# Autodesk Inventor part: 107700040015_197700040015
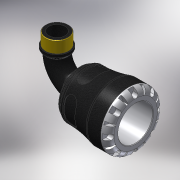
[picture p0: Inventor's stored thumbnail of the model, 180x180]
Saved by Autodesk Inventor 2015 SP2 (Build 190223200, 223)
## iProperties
Created: 2016-12
Part Number: 107700040015_197700040015
Material: PVC-Piping
Description: PLASSON 90° ELBOW WITH MALE INTEGRAL BRASS 40X1.1/2" SERIES 1
Document SubType Name: Modeling
Designer: KIM
Mass: 664.223 g
Surface Area: 733.008 cm^2
Volume: 474.445 cm^3
Density: 1.4 g/cm^3
Appearance: Black Cast
Author: KIM
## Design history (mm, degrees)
derived "1077.ipt"
feature "Solid1::1077.ipt"
tag "TaggingFeature1"
body "Solid1"
other parameters: "d1" = 29.82, "d8" = 59.5, "d13" = 8, "d14" = 8, "d15" = 0, "d17" = 360 deg, "d19" = 8 deg, "d20" = 0.8, "d21" = 0.8, "d22" = 8 deg, "d24" = 0, "d26" = 360 deg, "d33" = 7, "d43" = 54.6, "d51" = 0.7, "d54" = 14, "d55" = 8.8, "d57" = 15.68, "d58" = 0, "d74" = 0, "d78" = 71, "d82" = 0.8, "d115" = 360 deg, "d207" = 90 deg, "d228" = 11.9, "d247" = 1.4, "d248" = 4.26, "d268" = 32.725, "d269" = 4.26, "d270" = 104, "d276" = 47.803, "d277" = 21, "d278" = 52.5833, "d279" = 73, "d280" = 27.3, "d281" = 7.17045, "d283" = 43.0227, "d286" = 0, "d287" = 0, "d288" = 33.4621, "d290" = 5.78865, "d292" = 30 deg, "d294" = 4.7803, "d296" = 30 deg, "l_" = 71, "A_" = 104, "A_1" = 73, "l_2" = 21, "R_" = 47.803, "d289" = 33.4621
